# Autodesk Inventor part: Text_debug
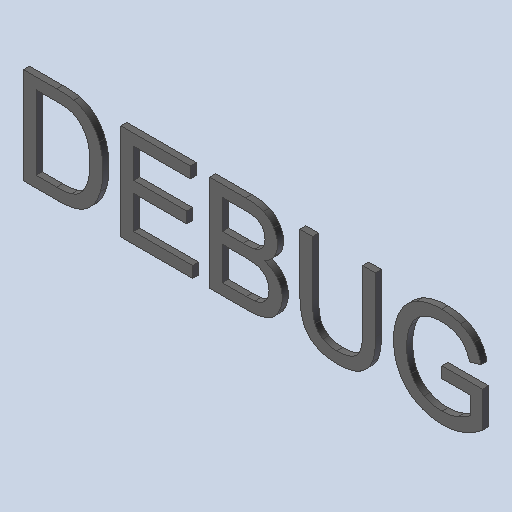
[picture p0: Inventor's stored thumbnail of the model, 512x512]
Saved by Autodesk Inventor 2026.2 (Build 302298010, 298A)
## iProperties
Created: 2026-10
Part Number: Text_debug
Material: Générique
Document SubType Name: Modeling
Designer: mel
Density: 1 g/cm^3
Appearance: Par défaut
Author: mel
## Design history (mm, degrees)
feature "Base1"
feature "Base2"
feature "Base3"
feature "Base4"
feature "Base5"
node "Solide1"
node "Solide2"
node "Solide3"
node "Solide4"
node "Solide5"
